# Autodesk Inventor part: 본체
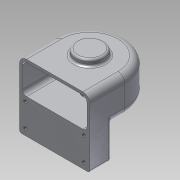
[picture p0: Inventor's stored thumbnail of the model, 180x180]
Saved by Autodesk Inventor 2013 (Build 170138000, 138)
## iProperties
Created: 2015-02
Part Number: 본체
Material: 알루미늄 6061
Document SubType Name: Modeling
Designer: Administrator
Density: 2.71 g/cm^3
Mass: 575.08 g
Surface Area: 707.668 cm^2
Volume: 212.207 cm^3
Author: Administrator
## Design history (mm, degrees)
sketch "스케치1"
  geometry: L1 (-50, 0)-(-50, -50); L2 (-50, -50)-(50, -50); L3 (50, -50)-(50, 0); A1 r 50 centre (0, 0) between (50, 0) and (-50, 0); 1 further point
  constraints: 6 end point, 2 point on circle, 2 tangent, 2 vertical, 1 centre point, 1 coincident, 1 perpendicular
  dimensions: "d0" = 50 radius of A1; "d1" = 50 distance from line of L2 point (0, 0)
extrude "돌출1" new body sketch "스케치1" distance "d2" = 50; taper "d3" = 0 deg
fillet "모깎기1" dims "d9" = 10
feature "쉘1" dims "d10" = 4
node "작업 평면1"
sketch "스케치3"
  geometry: L1 (-50, 0)-(-50, -50) reference; L2 (-40, -50)-(-50, -50) reference; L3 (-40, -50)-(40, -50) reference; L4 (50, -50)-(40, -50) reference; L5 (50, -50)-(50, 0) reference; L6 (-50, -20)-(-34.641, -20); L7 (34.641, -20)-(50, -20); A1 r 40 centre (0, 0) between (-34.641, -20) and (34.641, -20); 1 further point
  constraints: 4 end point, 2 perpendicular, 2 point on circle, 2 point on line, 1 centre point, 1 coincident
  dimensions: "d12" = 40 radius of A1; "d13" = 30 distance between parallel lines of L2 L6; "d14" = 30 distance between parallel lines of L4 L7
extrude "돌출2" join sketch "스케치3" stored distance "d15" = 45; taper "d16" = 0 deg
sketch "스케치4"
  geometry: C1 r 25 at (0, 0); A1 r 40 centre (0, 0) between (-34.641, -20) and (34.641, -20) reference
  constraints: 1 centre point, 1 coincident
  dimensions: "d17" = 50 diameter of C1
extrude "돌출3" join sketch "스케치4" distance "d19" = 10; taper "d20" = 0 deg
sketch "스케치5"
  geometry: C1 r 20 at (0, 0); A1 r 40 centre (0, 0) between (40, 0) and (-40, 0) reference
  constraints: 1 centre point, 1 coincident
  dimensions: "d21" = 40 diameter of C1
extrude "돌출4" join sketch "스케치5" distance "d23" = 9; taper "d24" = 0 deg
hole "구멍1" diameter "d27" = 20; stored, may be unused: countersink angle "d31" = 90 deg, drill point angle "d33" = 0 deg; dims "d25" = 10, "d26" = 10, "d28" = 6, "d29" = 28, "d30" = 10, "d32" = 8
hole "구멍2" diameter "d36" = 20; stored, may be unused: countersink angle "d40" = 90 deg, drill point angle "d42" = 0 deg; dims "d34" = 10, "d35" = 10, "d37" = 6, "d38" = 28, "d39" = 8, "d41" = 2
sketch "스케치6"
  geometry: C1 r 14 at (0, 0) reference; 1 further point
  constraints: 1 vertical alignment
  dimensions: "d43" = 18 distance of C1.centre point (0, 18)
hole "구멍3" sketch "스케치6" at (0, 18) diameter "d44" = 2.459; stored, may be unused: countersink angle "d48" = 90 deg, drill point angle "d50" = 118 deg; dims "d45" = 6, "d46" = 4, "d47" = 2, "d49" = 9
fillet "모깎기2" dims "d54" = 0.3
chamfer "모따기1" distance "d55" = 10; stored, may be unused: second distance "d56" = 2, angle "d57" = 20 deg
chamfer "모따기2" distance "d58" = 1; stored, may be unused: second distance "d59" = 2, angle "d60" = 20 deg
node "작업 평면2"
sketch "스케치7"
  geometry: L1 (-40, 50)-(40, 50) reference; 2 further points
  constraints: 1 vertical alignment, 1 other
  dimensions: "d61" = 25 distance from line of point (0, 25) L1
feature "엠보싱1" sketch "스케치7" dims "d62" = 0.5, "d63" = 0
sketch "스케치8"
  geometry: L1 (90, -95)-(-10, -95) reference; L2 (-1.75, -86)-(81.75, -86); L3 (81.75, -86)-(81.75, -53); L4 (81.75, -53)-(-1.75, -53); L5 (-1.75, -53)-(-1.75, -86); L6 (-1.75, -86)-(81.75, -53); L7 (81.75, -86)-(-1.75, -53); 7 further points
  constraints: 12 end point, 4 coincident, 3 midpoint, 2 parallel, 1 horizontal, 1 perpendicular, 1 vertical alignment
  dimensions: "d64" = 83.5 distance of L3.end L4.end; "d66" = 33 distance of L2.end L3.end; "d67" = 9 distance between parallel lines of L1 L2
hole "구멍4" sketch "스케치8" at (-1.75, -53), (-1.75, -86), (81.75, -86), (81.75, -53) diameter "d68" = 5.134; stored, may be unused: countersink angle "d72" = 90 deg, drill point angle "d74" = 118 deg; dims "d69" = 10, "d70" = 4, "d71" = 2, "d73" = 13
fillet "모깎기3" dims "d75" = 3
node "솔리드1"
pattern_circular "원형 패턴1" dims angle "d52" = 360 deg
other parameters: "d11" = 45
